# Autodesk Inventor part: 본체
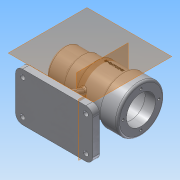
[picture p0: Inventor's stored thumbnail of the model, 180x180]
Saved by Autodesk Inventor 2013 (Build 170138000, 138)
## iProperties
Created: 2016-06
Part Number: 본체
Material: 알루미늄 6061
Document SubType Name: Modeling
Designer: Administrator
Mass: 670.414 g
Surface Area: 631.805 cm^2
Volume: 247.385 cm^3
Density: 2.71 g/cm^3
Author: Administrator
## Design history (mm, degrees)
sketch "스케치1"
  geometry: L1 (-35, -70)-(35, -70); L2 (-35, -70)-(-35, -60); L3 (-35, -60)-(35, -60); L4 (35, -60)-(35, -70); L5 (43.243, 5.419)-(-43.243, 5.419); L6 (72.217, 26.419)-(57.217, 26.419); L7 (57.217, 26.419)-(57.217, 29.419); L8 (57.217, 29.419)-(3.217, 29.419); L9 (3.217, 29.419)-(3.217, 22.919); L10 (3.217, 22.919)-(-8.783, 22.919); L11 (-8.783, 22.919)-(-8.783, 21.419); L12 (-8.783, 21.419)-(-26.783, 21.419); L13 (-26.783, 21.419)-(-26.783, 15.919); L14 (-39.783, 5.419)-(-39.783, 30.419); L15 (-39.783, 30.419)-(-14.783, 30.419); L16 (-14.783, 30.419)-(-14.783, 32.419); L17 (-14.783, 32.419)-(5.217, 32.419); L18 (5.217, 32.419)-(5.217, 35.419); L19 (5.217, 35.419)-(44.217, 35.419); L20 (44.217, 35.419)-(44.217, 39.419); L21 (44.217, 39.419)-(72.217, 39.419); L22 (72.217, 26.419)-(72.217, 39.419); L23 (-26.783, 15.919)-(-29.605, 15.919); L24 (-29.605, 15.919)-(-29.605, 5.419); L25 (-29.605, 5.419)-(-39.783, 5.419); 3 further points
  constraints: 50 end point, 6 perpendicular, 4 parallel, 2 midpoint, 2 vertical alignment, 1 collinear, 1 horizontal, 1 point on line
  dimensions: "d0" = 70 distance of point (0, 0) point (0, -70); "d1" = 70 distance of L1.start L1.end; "d2" = 10 distance of L1.start L2.end; "d8" = 48 diameter of L7.end L5; "d9" = 35 diameter of L9.end L5; "d11" = 32 diameter of L11.end L5; "d12" = 21 diameter of L13.end L5; "d14" = 18 distance of L11.end L12.end; "d15" = 12 distance of L9.end L10.end; "d16" = 54 distance of L7.end L8.end; "d20" = 42 diameter of L6.start L5; "d22" = 68 diameter of L21.end L5; "d23" = 15 distance of L6.start L6.end; "d24" = 50 diameter of L14.end L5; "d25" = 25 distance of L14.end L15.end; "d26" = 54 diameter of L16.end L5; "d27" = 20 distance of L16.end L17.end; "d28" = 60 diameter of L18.end L5; "d29" = 39 distance of L18.end L19.end; "d30" = 28 distance of L20.end L21.end; "d31" = 21 diameter of L23.end L5 (derived)
revolve "회전1" sketch "스케치1" stored, may be unused: angle "d32" = 90 deg
node "작업 평면1"
sketch "스케치3"
  geometry: L1 (-35, -60)-(35, -60); L2 (35, -60)-(35, -70); L3 (35, -70)-(-35, -70); L4 (-35, -70)-(-35, -60); C1 r 34 at (0, 0) reference; 2 further points
  constraints: 8 end point, 2 parallel, 1 horizontal, 1 midpoint, 1 perpendicular, 1 vertical alignment
  dimensions: "d34" = 70 distance of L2.end L3.end; "d36" = 10 distance of L1.end L2.end; "d37" = 70 distance from line of L3 C1.centre
extrude "돌출1" join sketch "스케치3" stored distance "d38" = 112; taper "d39" = 0 deg
node "작업 평면2"
sketch "스케치4"
  geometry: L1 (-35, -60)-(35, -60) reference; L2 (-35, -70)-(-35, -60) reference; L3 (35, -70)-(-35, -70) reference; L4 (-12.807, -27.129)-(-25, -60); L5 (14.287, -26.379)-(25, -60); L6 (25, -60)-(0, -60); L7 (0, -30)-(0, -60); L8 (0, -30)-(14.287, -26.379); A1 r 30 centre (0, 0) between (-12.807, -27.129) and (14.287, -26.379) reference; 1 further point
  constraints: 10 end point, 3 point on circle, 2 coincident, 2 point on line, 1 midpoint, 1 perpendicular
  dimensions: "d43" = 25 horizontal distance of L4.end A1.centre; "d44" = 25 horizontal distance of L5.end A1.centre
extrude "돌출2" join sketch "스케치4" stored distance "d45" = 10; taper "d46" = 0 deg
sketch "스케치5"
  geometry: L1 (0, -29.949)-(-12.744, -27.297); 1 further point
  constraints: 2 end point
extrude "돌출3" join sketch "스케치4" stored distance "d47" = 10; taper "d48" = 0 deg
node "작업 평면3"
sketch "스케치6"
  geometry: L1 (0, 0)-(112, 0) reference; L2 (0, -10)-(0, 0) reference; L3 (0, -10)-(112, -10) reference; L4 (112, 0)-(112, -10) reference; 1 further point
sketch "스케치7"
  geometry: L1 (-35, -60)-(35, -60) reference; L2 (-35, -70)-(-35, -60) reference; L3 (35, -70)-(-35, -70) reference; L4 (-25, -60)-(25, -60) reference; L5 (0, -60)-(-4, -60); L6 (-4, -60)-(-4, -25.072); L7 (-4, -25.072)-(0, -25.072); L8 (0, -25.072)-(0, -60); L9 (0, -60)-(4, -60); L10 (4, -60)-(4, -25.072); L11 (4, -25.072)-(0, -25.072); L12 (0, -25.072)-(0, -60); 1 further point
  constraints: 16 end point, 4 parallel, 2 horizontal, 2 perpendicular, 1 midpoint
  dimensions: "d50" = 35 distance of L1.start L5.start (derived); "d51" = 4 distance of L6.end L7.end; "d52" = 4 distance of L11.end L10.end
sketch "스케치8"
  geometry: C1 r 21 at (0, 0) reference; C2 r 34 at (0, 0) reference; C3 r 26 at (0, 0); 2 further points
  constraints: 1 centre point, 1 coincident, 1 vertical alignment
  dimensions: "d53" = 52 diameter of C3; "d55" = 26 distance of C1.centre point (0, 26)
hole "구멍1" sketch "스케치8" at (0, 26) diameter "d56" = 3.459; stored, may be unused: countersink angle "d60" = 90 deg, drill point angle "d62" = 118 deg; dims "d57" = 8, "d58" = 4, "d59" = 2, "d61" = 11
sketch "스케치9"
  geometry: L1 (112, 70)-(112, 0) reference; L2 (112, 70)-(0, 70) reference; 2 further points
  dimensions: "d66" = 10 distance from line of L1 point (102, 60); "d67" = 10 distance from line of L2 point (102, 60)
fillet "모깎기1" dims "d68" = 10
sketch "스케치10"
  geometry: A1 r 10 centre (92, 10) between (92, 0) and (102, 10) reference; 1 further point
hole "구멍2" sketch "스케치9" diameter "d69" = 7; stored, may be unused: countersink angle "d73" = 90 deg, drill point angle "d75" = 0 deg; dims "d70" = 8, "d71" = 4, "d72" = 2, "d74" = 10
hole "구멍3" sketch "스케치10" diameter "d76" = 7; stored, may be unused: countersink angle "d80" = 90 deg, drill point angle "d82" = 0 deg; dims "d77" = 8, "d78" = 4, "d79" = 2, "d81" = 10
sketch "스케치11"
  geometry: A1 r 10 centre (0, 60) between (0, 70) and (-10, 60) reference; 1 further point
hole "구멍4" sketch "스케치11" at (0, 60) diameter "d83" = 7; stored, may be unused: countersink angle "d87" = 90 deg, drill point angle "d89" = 0 deg; dims "d84" = 8, "d85" = 4, "d86" = 2, "d88" = 10
sketch "스케치12"
  geometry: A1 r 10 centre (0, 10) between (-10, 10) and (0, 0) reference; 1 further point
hole "구멍5" sketch "스케치12" at (0, 10) diameter "d90" = 7; stored, may be unused: countersink angle "d94" = 90 deg, drill point angle "d96" = 0 deg; dims "d91" = 8, "d92" = 4, "d93" = 2, "d95" = 10
fillet "모깎기2" dims "d97" = 3
node "작업 평면4"
sketch "스케치13"
  geometry: 2 further points
  constraints: 1 other
feature "엠보싱1" sketch "스케치13" dims "d0" = 70, "d1" = 70, "d2" = 10, "d8" = 48, "d9" = 35, "d11" = 32, "d12" = 21, "d14" = 18, "d15" = 12, "d16" = 54, "d20" = 42, "d22" = 68, "d23" = 15, "d24" = 50, "d25" = 25, "d26" = 54, "d27" = 20, "d28" = 60, "d29" = 39, "d30" = 28, "d31" = 21 (derived), "d99" = 0.5, "d100" = 0
node "솔리드1"
pattern_circular "원형 패턴1" dims angle "d64" = 360 deg
other parameters: "d33" = -56, "d40" = -56
